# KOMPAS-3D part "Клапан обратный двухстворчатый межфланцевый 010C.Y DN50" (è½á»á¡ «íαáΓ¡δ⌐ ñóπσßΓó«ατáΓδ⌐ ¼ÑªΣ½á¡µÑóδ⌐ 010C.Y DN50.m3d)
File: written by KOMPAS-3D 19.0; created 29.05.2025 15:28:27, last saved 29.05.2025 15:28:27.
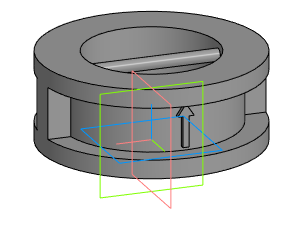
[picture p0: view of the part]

Document properties: Полное имя файла: E:\Dendor Работа Сачек\3D для проекитирвщиков\5.2 Тип 010C, 010C.Y Клапан обратный двухстворчатый межфланцевый\stp_Клапан обратный двухстворчатый межфланцевый 010C.Y\Клапан обратный двухстворчатый межфланцевый 010C.Y DN50.m3d

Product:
- Part/product: Клапан обратный двухстворчатый межфланцевый 010C.Y DN50

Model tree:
1. Операция без истории:1  (labels: Клапан обратный двухстворчатый межфланцевый 010C.Y DN50)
